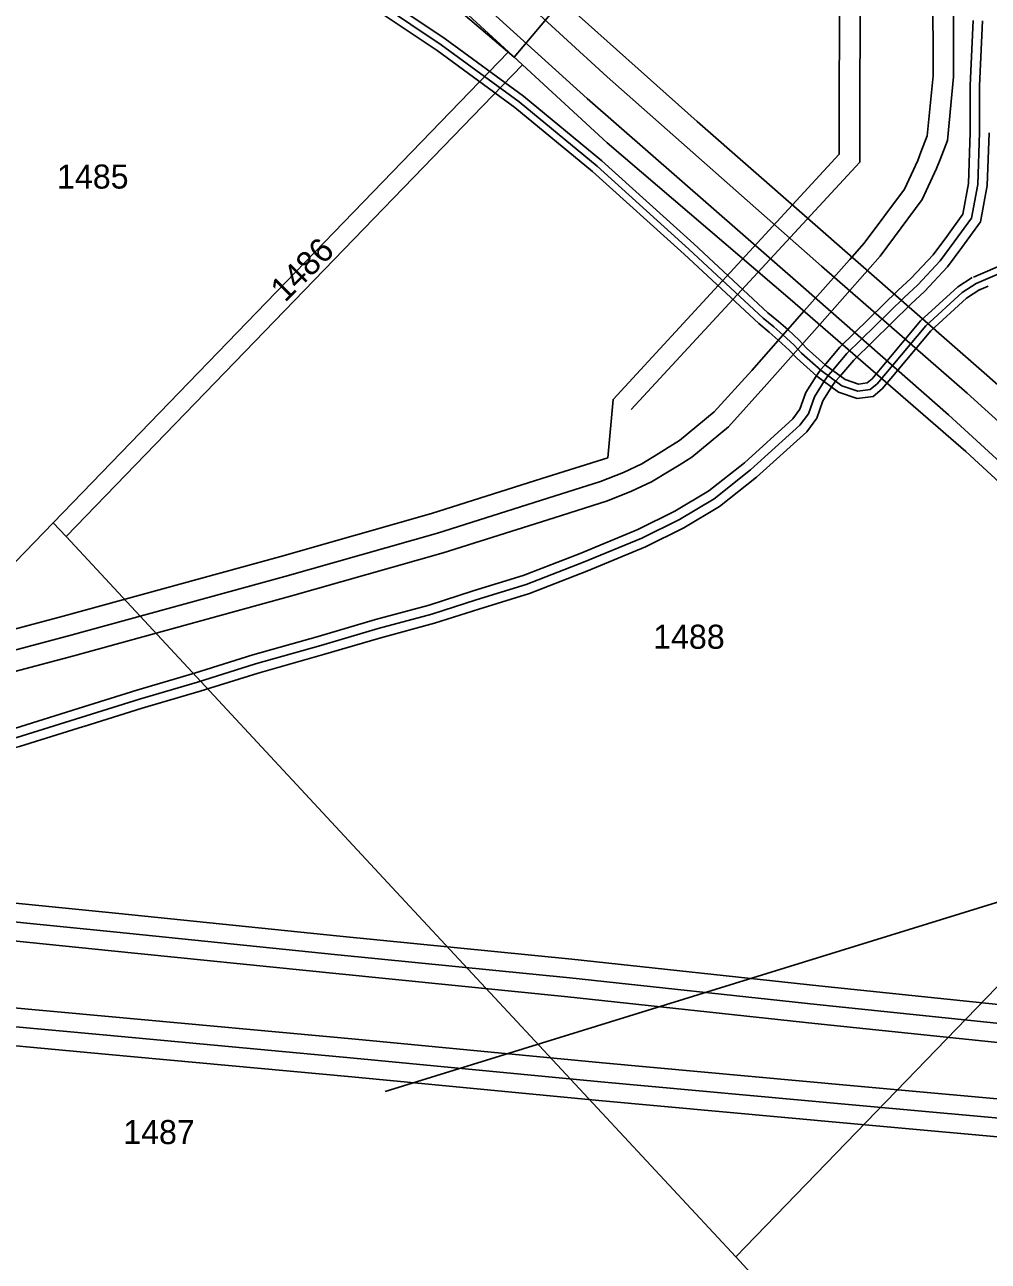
# Model space of a CAD drawing. Extents: x -510185 to -506993, y -1126306 to -1123642.
# Drawn here: x -509972.3 to -509767.9, y -1125617.7 to -1125355.5 of the extents above; entities that cross this region are included whole.
import ezdxf

# ---------------------------------------------------------------- set-up
doc = ezdxf.new("R2010")
doc.units = 0
for name, color, linetype in [('Net4gas', 7, 'Continuous'), ('parcelni hranice', 7, 'Continuous'), ('telefonica', 7, 'Continuous'), ('u_dalnice', 7, 'Continuous'), ('u_kabely', 7, 'Continuous'), ('u_net4gas', 7, 'Continuous'), ('u_plyn ochranné pásmo', 7, 'Continuous'), ('u_plyn VTL', 7, 'Continuous'), ('u_prijezd', 7, 'Continuous'), ('u_sitel_self_net4', 7, 'Continuous'), ('u_Telefonica', 7, 'Continuous'), ('ˇ2', 7, 'Continuous'), ('ˇ4', 7, 'Continuous')]:
    doc.layers.add(name, color=color, linetype=linetype)

msp = doc.modelspace()

# ---------------------------------------------------------------- linework, layer by layer
at = {"layer": 'Net4gas'}
for p, q in [((-509778.14, -1125384.09), (-509778.14, -1125384.1)), ((-509794.1, -1125408.24), (-509794.05, -1125408.18)), ((-509794.08, -1125408.23), (-509794.1, -1125408.24)), ((-509794.05, -1125408.18), (-509794.03, -1125408.17)), ((-509835.66, -1125450.19), (-509835.66, -1125450.19))]:
    msp.add_line(p, q, dxfattribs=at)
for points in [[(-509848.66, -1125447.37), (-509847.51, -1125434.96), (-509799.55, -1125382.98), (-509798.81, -1124945.67), (-509798.75, -1124907.97), (-508222.29, -1123973.97), (-508155.01, -1123999.2), (-508080.5, -1123953.99), (-508072.94, -1123908.62)], [(-509778.14, -1125384.1), (-509776.59, -1125380.08), (-509775.27, -1125366.56), (-509775.4, -1125327.96), (-509775.81, -1125301.88), (-509776.64, -1125270.13), (-509777.19, -1125251.11), (-509777.71, -1125221.73), (-509778.27, -1125189.62), (-509778.35, -1125154.75)], [(-509794.03, -1125408.17), (-509790.86, -1125404.59), (-509781.95, -1125392.59), (-509778.88, -1125386), (-509778.14, -1125384.09)], [(-509835.66, -1125450.19), (-509833.5, -1125448.88), (-509830.85, -1125447.18), (-509823.04, -1125440.79), (-509814.87, -1125431.74), (-509803.69, -1125419.06), (-509794.08, -1125408.23)], [(-510185.05, -1125536.53), (-510171.45, -1125533.15), (-510118.64, -1125519.73), (-510034.51, -1125499.78), (-510017.05, -1125494.96), (-509964.2, -1125480.91), (-509918.3, -1125468.33), (-509886.05, -1125459.17), (-509862.65, -1125451.75), (-509848.66, -1125447.37)], [(-510185.05, -1125545.5), (-510169.33, -1125541.59), (-510116.57, -1125528.18), (-510032.35, -1125508.21), (-510014.78, -1125503.35), (-509961.93, -1125489.31), (-509915.96, -1125476.71), (-509883.55, -1125467.5), (-509860.03, -1125460.04), (-509848.72, -1125456.5), (-509843.6, -1125454.45), (-509839.38, -1125452.47), (-509835.66, -1125450.19)]]:
    msp.add_lwpolyline(points, dxfattribs=at)
at = {"layer": 'parcelni hranice'}
for p, q in [((-509894.28, -1125318.26), (-509829.71, -1125376.03)), ((-509890.9, -1125341.77), (-509869.68, -1125361.29)), ((-509966.3, -1125461.11), (-509869.68, -1125361.29)), ((-509866.73, -1125364), (-509869.68, -1125361.29)), ((-509866.73, -1125364), (-509963.57, -1125464.04)), ((-509866.73, -1125364), (-509848.75, -1125380.53)), ((-509760.05, -1125437.04), (-509829.71, -1125376.03)), ((-509809.99, -1125413.68), (-509848.75, -1125380.53)), ((-509809.99, -1125413.68), (-509772.66, -1125445.97)), ((-509772.66, -1125445.97), (-509739.21, -1125477.02)), ((-510023.75, -1125520.46), (-509966.3, -1125461.11)), ((-509966.3, -1125461.11), (-509963.57, -1125464.04)), ((-509892.54, -1125540.4), (-509963.57, -1125464.04)), ((-509713.26, -1125504.94), (-509821.5, -1125616.77)), ((-509892.54, -1125540.4), (-509821.5, -1125616.77)), ((-509821.5, -1125616.77), (-509787.95, -1125652.83))]:
    msp.add_line(p, q, dxfattribs=at)
at = {"layer": 'telefonica'}
for p, q in [((-509771.09, -1125409.01), (-509769.09, -1125408.17)), ((-509769.93, -1125411.77), (-509767.93, -1125410.93))]:
    msp.add_line(p, q, dxfattribs=at)
for points in [[(-509902.73, -1125345.36), (-509883.14, -1125358.52), (-509866.5, -1125370.69), (-509849.9, -1125384.38), (-509830.41, -1125401.97), (-509814.67, -1125416.61), (-509812.45, -1125418.41), (-509810.48, -1125420.17), (-509808.03, -1125422.4), (-509806.47, -1125424.08), (-509802.45, -1125427.69), (-509798.27, -1125430.72), (-509795.44, -1125431.7), (-509793.59, -1125431.46), (-509792.57, -1125430.59), (-509782.27, -1125418.33), (-509774.41, -1125411.09), (-509771.31, -1125409.12)], [(-509904.35, -1125347.88), (-509884.86, -1125360.98), (-509868.34, -1125373.05), (-509851.86, -1125386.66), (-509832.43, -1125404.19), (-509816.63, -1125418.87), (-509814.39, -1125420.69), (-509812.5, -1125422.39), (-509810.15, -1125424.54), (-509808.57, -1125426.22), (-509804.33, -1125430.03), (-509799.67, -1125433.4), (-509795.76, -1125434.76), (-509792.33, -1125434.32), (-509790.43, -1125432.71), (-509780.09, -1125420.41), (-509772.57, -1125413.47), (-509769.71, -1125411.66)], [(-509769.1, -1125408.17), (-509739.56, -1125395.5), (-509694.19, -1125377.12), (-509693.21, -1125376.81), (-509690.91, -1125374.62), (-509670.5, -1125366.82), (-509634.2, -1125353.26)]]:
    msp.add_lwpolyline(points, dxfattribs=at)
at = {"layer": 'u_dalnice'}
msp.add_lwpolyline([(-509087.92, -1125269.66), (-509370.63, -1125404.12), (-509625.72, -1125498.22), (-509895.89, -1125581.7)], dxfattribs=at)
at = {"layer": 'u_kabely'}
for points in [[(-509961.04, -1125500.52), (-509948.58, -1125496.63), (-509936.3, -1125492.98), (-509923.98, -1125489.13), (-509910.07, -1125485.2), (-509897.9, -1125481.62), (-509886.56, -1125478.59), (-509877.2, -1125475.58), (-509866.6, -1125472.32), (-509854.54, -1125467.64), (-509842.28, -1125462.56), (-509834.42, -1125458.68), (-509827.21, -1125454.36), (-509819.67, -1125448.39), (-509809.4, -1125439.1), (-509807.87, -1125437.05), (-509806.62, -1125433.53), (-509804.43, -1125430.02), (-509803.47, -1125428.64), (-509802.41, -1125427.45), (-509799.41, -1125423.9), (-509787.14, -1125411.87), (-509784.26, -1125409.23), (-509779.63, -1125404.28), (-509776.74, -1125400.4), (-509773.35, -1125395.7), (-509772.11, -1125389.17), (-509771.77, -1125378.37), (-509771.8, -1125368.4), (-509771.12, -1125354.61)], [(-509959.84, -1125504.34), (-509947.42, -1125500.45), (-509935.14, -1125496.8), (-509922.84, -1125492.97), (-509908.97, -1125489.04), (-509896.82, -1125485.48), (-509885.44, -1125482.43), (-509876, -1125479.4), (-509865.28, -1125476.1), (-509853.06, -1125471.36), (-509840.62, -1125466.2), (-509832.5, -1125462.2), (-509824.93, -1125457.66), (-509817.09, -1125451.45), (-509806.44, -1125441.8), (-509804.31, -1125438.97), (-509803, -1125435.29), (-509801.08, -1125432.22), (-509800.33, -1125431.12), (-509799.39, -1125430.07), (-509796.48, -1125426.62), (-509784.39, -1125414.77), (-509781.44, -1125412.07), (-509776.56, -1125406.85), (-509773.52, -1125402.76), (-509769.59, -1125397.32), (-509768.13, -1125389.61), (-509767.77, -1125378.43)], [(-510185.05, -1125553.4), (-510171.14, -1125549.71), (-510150.63, -1125544.87), (-510127.22, -1125539.2), (-510110.21, -1125535.2), (-510095.82, -1125532.21), (-510081.26, -1125528.18), (-510066.1, -1125524.62), (-510060.33, -1125522.77), (-510052.05, -1125521.17), (-510039.1, -1125518.99), (-510036.06, -1125518.29), (-510026.33, -1125516.41), (-510023.46, -1125515.99), (-510011.4, -1125513.73), (-510000.55, -1125511.28), (-509987.12, -1125507.77), (-509974.54, -1125504.72), (-509961.03, -1125500.52)], [(-510185.05, -1125557.54), (-510170.16, -1125553.59), (-510149.71, -1125548.77), (-510126.3, -1125543.1), (-510109.35, -1125539.1), (-510094.88, -1125536.09), (-510080.26, -1125532.06), (-510065.04, -1125528.48), (-510059.33, -1125526.65), (-510051.33, -1125525.11), (-510038.32, -1125522.91), (-510035.24, -1125522.21), (-510025.65, -1125520.35), (-510022.8, -1125519.93), (-510010.6, -1125517.65), (-509999.61, -1125515.16), (-509986.14, -1125511.65), (-509973.48, -1125508.58), (-509959.85, -1125504.34)]]:
    msp.add_lwpolyline(points, dxfattribs=at)
at = {"layer": 'u_net4gas'}
msp.add_line((-509797.34, -1125405.34), (-509797.29, -1125405.29), dxfattribs=at)
for points in [[(-509843.66, -1125437.1), (-509795.2, -1125384.69), (-509794.46, -1124945.67), (-509794.41, -1124910.45), (-508221.87, -1123978.78), (-508154.56, -1124004.01), (-508076.54, -1123956.67), (-508068.65, -1123909.34)], [(-509782.2, -1125382.53), (-509780.86, -1125379.06), (-509779.62, -1125366.36), (-509779.75, -1125328), (-509780.16, -1125301.97), (-509780.98, -1125270.26), (-509781.54, -1125251.21), (-509782.06, -1125221.81), (-509782.62, -1125189.67), (-509782.7, -1125154.76)], [(-509797.29, -1125405.29), (-509794.24, -1125401.84), (-509785.7, -1125390.35), (-509782.88, -1125384.3), (-509782.2, -1125382.53)], [(-509837.93, -1125446.48), (-509835.81, -1125445.19), (-509833.41, -1125443.65), (-509826.05, -1125437.63), (-509818.11, -1125428.84), (-509806.95, -1125416.18), (-509797.34, -1125405.34)], [(-510185.05, -1125541.01), (-510170.39, -1125537.37), (-510117.6, -1125523.96), (-510033.43, -1125503.99), (-510015.92, -1125499.15), (-509963.07, -1125485.11), (-509917.13, -1125472.52), (-509884.8, -1125463.34), (-509861.34, -1125455.9), (-509850.18, -1125452.4), (-509845.33, -1125450.46), (-509841.45, -1125448.64), (-509837.93, -1125446.48)]]:
    msp.add_lwpolyline(points, dxfattribs=at)
at = {"layer": 'u_plyn ochranné pásmo'}
for points in [[(-509992.05, -1125539.97), (-509953.11, -1125543.89), (-509905.52, -1125548.74), (-509856.27, -1125553.65), (-509803.9, -1125559.29), (-509751.48, -1125564.75), (-509698.26, -1125570.2), (-509695.79, -1125571.28), (-509694.51, -1125572.61), (-509694.19, -1125572.95), (-509693.71, -1125573.76), (-509693.58, -1125574.21), (-509683.32, -1125607.62), (-509678.3, -1125624.87)], [(-509685.98, -1125627.09), (-509690.98, -1125609.92), (-509700.78, -1125577.99), (-509752.3, -1125572.71), (-509804.74, -1125567.25), (-509857.09, -1125561.61), (-509906.32, -1125556.7), (-509953.91, -1125551.85), (-509992.81, -1125547.93)], [(-509989.44, -1125562.6), (-509954.56, -1125565.8), (-509902.18, -1125570.63), (-509849.78, -1125575.65), (-509797.2, -1125580.46), (-509754.38, -1125584.33), (-509715.09, -1125587.61), (-509712.57, -1125587.91), (-509710.17, -1125589.23), (-509708.54, -1125591.32), (-509707.85, -1125593.36), (-509696.93, -1125630.29)], [(-509704.61, -1125632.57), (-509715.47, -1125595.78), (-509715.53, -1125595.61), (-509715.89, -1125595.57), (-509755.08, -1125592.3), (-509797.92, -1125588.42), (-509850.52, -1125583.61), (-509902.92, -1125578.59), (-509955.3, -1125573.76), (-509990.18, -1125570.56)]]:
    msp.add_lwpolyline(points, dxfattribs=at)
at = {"layer": 'u_plyn VTL'}
for points in [[(-509698.12, -1125574.63), (-509699.29, -1125574.12), (-509751.89, -1125568.73), (-509804.32, -1125563.27), (-509856.68, -1125557.63), (-509905.92, -1125552.72), (-509953.51, -1125547.87), (-509992.43, -1125543.95), (-510035.76, -1125540.06), (-510050.14, -1125538.71), (-510084.77, -1125534.71), (-510093.36, -1125533.73), (-510094.46, -1125533.61), (-510110.36, -1125531.67), (-510111.07, -1125531.58)], [(-510144.65, -1125552.35), (-510111.71, -1125555.47), (-510076.59, -1125558.66), (-510051.05, -1125560.97), (-510043.38, -1125561.6), (-510035.75, -1125562.3), (-509989.81, -1125566.58), (-509954.93, -1125569.78), (-509902.55, -1125574.61), (-509850.15, -1125579.63), (-509797.56, -1125584.44), (-509754.73, -1125588.32), (-509715.49, -1125591.59), (-509713.82, -1125591.79), (-509712.82, -1125592.34)]]:
    msp.add_lwpolyline(points, dxfattribs=at)
at = {"layer": 'u_prijezd'}
msp.add_line((-509868.53, -1125362.37), (-509894.65, -1125340.15), dxfattribs=at)
msp.add_lwpolyline([(-509860.85, -1125353.36), (-509868.53, -1125362.37)], dxfattribs=at)
at = {"layer": 'u_sitel_self_net4'}
for points in [[(-509960.44, -1125502.43), (-509948, -1125498.54), (-509935.72, -1125494.89), (-509923.41, -1125491.05), (-509909.52, -1125487.12), (-509897.36, -1125483.55), (-509886, -1125480.51), (-509876.6, -1125477.49), (-509865.94, -1125474.21), (-509853.8, -1125469.5), (-509841.45, -1125464.38), (-509833.46, -1125460.44), (-509826.07, -1125456.01), (-509818.38, -1125449.92), (-509807.92, -1125440.45), (-509806.09, -1125438.01), (-509804.81, -1125434.41), (-509802.75, -1125431.12), (-509801.9, -1125429.88), (-509800.9, -1125428.76), (-509797.95, -1125425.26), (-509785.77, -1125413.32), (-509782.85, -1125410.65), (-509778.1, -1125405.56), (-509775.13, -1125401.58), (-509771.47, -1125396.51), (-509770.12, -1125389.39), (-509769.77, -1125378.4), (-509769.8, -1125368.45), (-509769.12, -1125354.72)], [(-509960.44, -1125502.43), (-509948, -1125498.54), (-509935.72, -1125494.89), (-509923.41, -1125491.05), (-509909.52, -1125487.12), (-509897.36, -1125483.55), (-509886, -1125480.51), (-509876.6, -1125477.49), (-509865.94, -1125474.21), (-509853.8, -1125469.5), (-509841.45, -1125464.38), (-509833.46, -1125460.44), (-509826.07, -1125456.01), (-509818.38, -1125449.92), (-509807.92, -1125440.45), (-509806.09, -1125438.01), (-509804.81, -1125434.41), (-509802.75, -1125431.12), (-509801.9, -1125429.88), (-509800.9, -1125428.76), (-509797.95, -1125425.26), (-509785.77, -1125413.32), (-509782.85, -1125410.65), (-509778.1, -1125405.56), (-509775.13, -1125401.58), (-509771.47, -1125396.51), (-509770.12, -1125389.39), (-509769.77, -1125378.4), (-509769.8, -1125368.45), (-509769.12, -1125354.72)], [(-509960.44, -1125502.43), (-509948, -1125498.54), (-509935.72, -1125494.89), (-509923.41, -1125491.05), (-509909.52, -1125487.12), (-509897.36, -1125483.55), (-509886, -1125480.51), (-509876.6, -1125477.49), (-509865.94, -1125474.21), (-509853.8, -1125469.5), (-509841.45, -1125464.38), (-509833.46, -1125460.44), (-509826.07, -1125456.01), (-509818.38, -1125449.92), (-509807.92, -1125440.45), (-509806.09, -1125438.01), (-509804.81, -1125434.41), (-509802.75, -1125431.12), (-509801.9, -1125429.88), (-509800.9, -1125428.76), (-509797.95, -1125425.26), (-509785.77, -1125413.32), (-509782.85, -1125410.65), (-509778.1, -1125405.56), (-509775.13, -1125401.58), (-509771.47, -1125396.51), (-509770.12, -1125389.39), (-509769.77, -1125378.4), (-509769.8, -1125368.45), (-509769.12, -1125354.72)], [(-510185.05, -1125555.47), (-510170.65, -1125551.65), (-510150.17, -1125546.82), (-510126.76, -1125541.15), (-510109.78, -1125537.15), (-510095.35, -1125534.15), (-510080.76, -1125530.12), (-510065.57, -1125526.55), (-510059.83, -1125524.71), (-510051.69, -1125523.14), (-510038.71, -1125520.95), (-510035.65, -1125520.25), (-510025.99, -1125518.38), (-510023.13, -1125517.96), (-510011, -1125515.69), (-510000.08, -1125513.22), (-509986.63, -1125509.71), (-509974.01, -1125506.65), (-509960.44, -1125502.43)], [(-510185.05, -1125555.47), (-510170.65, -1125551.65), (-510150.17, -1125546.82), (-510126.76, -1125541.15), (-510109.78, -1125537.15), (-510095.35, -1125534.15), (-510080.76, -1125530.12), (-510065.57, -1125526.55), (-510059.83, -1125524.71), (-510051.69, -1125523.14), (-510038.71, -1125520.95), (-510035.65, -1125520.25), (-510025.99, -1125518.38), (-510023.13, -1125517.96), (-510011, -1125515.69), (-510000.08, -1125513.22), (-509986.63, -1125509.71), (-509974.01, -1125506.65), (-509960.44, -1125502.43)], [(-510185.05, -1125555.47), (-510170.65, -1125551.65), (-510150.17, -1125546.82), (-510126.76, -1125541.15), (-510109.78, -1125537.15), (-510095.35, -1125534.15), (-510080.76, -1125530.12), (-510065.57, -1125526.55), (-510059.83, -1125524.71), (-510051.69, -1125523.14), (-510038.71, -1125520.95), (-510035.65, -1125520.25), (-510025.99, -1125518.38), (-510023.13, -1125517.96), (-510011, -1125515.69), (-510000.08, -1125513.22), (-509986.63, -1125509.71), (-509974.01, -1125506.65), (-509960.44, -1125502.43)]]:
    msp.add_lwpolyline(points, dxfattribs=at)
at = {"layer": 'u_Telefonica'}
for p, q in [((-509770.51, -1125410.39), (-509768.51, -1125409.55)), ((-509770.51, -1125410.39), (-509768.51, -1125409.55)), ((-509770.51, -1125410.39), (-509768.51, -1125409.55)), ((-509770.51, -1125410.39), (-509768.51, -1125409.55)), ((-509791.5, -1125431.65), (-509781.18, -1125419.37)), ((-509791.5, -1125431.65), (-509781.18, -1125419.37))]:
    msp.add_line(p, q, dxfattribs=at)
for points in [[(-509903.54, -1125346.62), (-509884, -1125359.75), (-509867.42, -1125371.87), (-509850.88, -1125385.52), (-509831.42, -1125403.08), (-509815.65, -1125417.74), (-509813.42, -1125419.55), (-509811.49, -1125421.28), (-509809.09, -1125423.47), (-509807.52, -1125425.15), (-509803.39, -1125428.86), (-509798.97, -1125432.06), (-509795.6, -1125433.23), (-509792.96, -1125432.89), (-509791.5, -1125431.65), (-509781.18, -1125419.37), (-509773.49, -1125412.28), (-509770.51, -1125410.39)], [(-509903.54, -1125346.62), (-509884, -1125359.75), (-509867.42, -1125371.87), (-509850.88, -1125385.52), (-509831.42, -1125403.08), (-509815.65, -1125417.74), (-509813.42, -1125419.55), (-509811.49, -1125421.28), (-509809.09, -1125423.47), (-509807.52, -1125425.15), (-509803.39, -1125428.86), (-509798.97, -1125432.06), (-509795.6, -1125433.23), (-509792.96, -1125432.89), (-509791.5, -1125431.65), (-509781.18, -1125419.37), (-509773.49, -1125412.28), (-509770.51, -1125410.39)], [(-509903.54, -1125346.62), (-509884, -1125359.75), (-509867.42, -1125371.87), (-509850.88, -1125385.52), (-509831.42, -1125403.08), (-509815.65, -1125417.74), (-509813.42, -1125419.55), (-509811.49, -1125421.28), (-509809.09, -1125423.47), (-509807.52, -1125425.15), (-509803.39, -1125428.86), (-509798.97, -1125432.06), (-509795.6, -1125433.23), (-509792.96, -1125432.89), (-509791.5, -1125431.65), (-509781.18, -1125419.37), (-509773.49, -1125412.28), (-509770.51, -1125410.39)], [(-509903.54, -1125346.62), (-509884, -1125359.75), (-509867.42, -1125371.87), (-509850.88, -1125385.52), (-509831.42, -1125403.08), (-509815.65, -1125417.74), (-509813.42, -1125419.55), (-509811.49, -1125421.28), (-509809.09, -1125423.47), (-509807.52, -1125425.15), (-509803.39, -1125428.86), (-509798.97, -1125432.06), (-509795.6, -1125433.23), (-509792.96, -1125432.89), (-509791.5, -1125431.65), (-509781.18, -1125419.37), (-509773.49, -1125412.28), (-509770.51, -1125410.39)], [(-509768.51, -1125409.55), (-509738.98, -1125396.88), (-509693.69, -1125378.53), (-509692.43, -1125378.14), (-509690.09, -1125375.91), (-509669.97, -1125368.22), (-509633.67, -1125354.66)], [(-509768.51, -1125409.55), (-509738.98, -1125396.88), (-509693.69, -1125378.53), (-509692.43, -1125378.14), (-509690.09, -1125375.91), (-509669.97, -1125368.22), (-509633.67, -1125354.66)], [(-509768.51, -1125409.55), (-509738.98, -1125396.88), (-509693.69, -1125378.53), (-509692.43, -1125378.14), (-509690.09, -1125375.91), (-509669.97, -1125368.22), (-509633.67, -1125354.66)], [(-509768.51, -1125409.55), (-509738.98, -1125396.88), (-509693.69, -1125378.53), (-509692.43, -1125378.14), (-509690.09, -1125375.91), (-509669.97, -1125368.22), (-509633.67, -1125354.66)], [(-509813.42, -1125419.55), (-509811.49, -1125421.28), (-509809.09, -1125423.47)], [(-509813.42, -1125419.55), (-509811.49, -1125421.28), (-509809.09, -1125423.47)]]:
    msp.add_lwpolyline(points, dxfattribs=at)
at = {"layer": 'ˇ4'}
for p, q in [((-509848.8, -1125366.56), (-509872.12, -1125345.15)), ((-509853.03, -1125371.15), (-509877.67, -1125348.81)), ((-509848.8, -1125366.56), (-509803.3, -1125406.71)), ((-509807.1, -1125411.2), (-509853.03, -1125371.15)), ((-509772.43, -1125433.63), (-509803.3, -1125406.71)), ((-509776.33, -1125438.26), (-509807.1, -1125411.2)), ((-509746.59, -1125457.12), (-509772.43, -1125433.63)), ((-509736.9, -1125474.47), (-509776.33, -1125438.26))]:
    msp.add_line(p, q, dxfattribs=at)

# ---------------------------------------------------------------- texts
at = {"layer": 'ˇ2'}
for s, p in [('1485', (-509965.49, -1125390.26)), ('1488', (-509839.02, -1125487.83)), ('1487', (-509951.44, -1125592.85))]:
    msp.add_text(s, height=5.1, dxfattribs=at).set_placement(p)
msp.add_text('1486', height=5.1, rotation=44.9772, dxfattribs=at).set_placement((-509917.1, -1125414.55))

doc.saveas('drawing.dxf')
